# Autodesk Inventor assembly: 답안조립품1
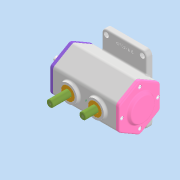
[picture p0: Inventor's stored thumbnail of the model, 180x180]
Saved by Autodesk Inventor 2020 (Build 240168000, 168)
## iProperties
Created: 2021-06
Part Number: 답안조립품1
Document SubType Name: Assembly
Designer: MIRAE
Author: MIRAE
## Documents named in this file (11)
- C:\Users\MIRAE\Desktop\710606V1019\710606V1019\답안조립품1.iam
- C:\Users\MIRAE\Documents\Inventor\710606V1019\본체.ipt
- C:\Users\MIRAE\Desktop\710606V1019\710606V1019\편심축.ipt
- C:\Users\MIRAE\Desktop\710606V1019\710606V1019\슬라이더.ipt
- C:\Users\MIRAE\Desktop\710606V1019\710606V1019\베어링 6302.ipt
- C:\Users\MIRAE\Desktop\710606V1019\710606V1019\뒷커버.ipt
- C:\Users\MIRAE\Desktop\710606V1019\710606V1019\베어링 6203.ipt
- C:\Users\MIRAE\Desktop\710606V1019\710606V1019\앞커버.ipt
- C:\Users\MIRAE\Desktop\710606V1019\710606V1019\오일실.ipt
- C:\Users\MIRAE\Desktop\710606V1019\710606V1019\부시.ipt
- C:\Users\MIRAE\Desktop\710606V1019\710606V1019\볼트 M4.ipt
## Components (10 placed, 3 different names)
1. 7-베어링 6203:1
2. 8-오일실:1
3. 9-M4-소켓머리:1
4. 9-M4-소켓머리:2
5. 9-M4-소켓머리:3
6. 9-M4-소켓머리:4
7. 9-M4-소켓머리:5
8. 9-M4-소켓머리:6
9. 9-M4-소켓머리:7
10. 9-M4-소켓머리:8
